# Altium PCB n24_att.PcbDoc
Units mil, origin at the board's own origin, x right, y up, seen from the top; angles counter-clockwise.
Board outline 1125 x 905 mil, 2 copper layers (Top Layer, Bottom Layer); 13 components, 14 nets, 48 pads, 11 vias.
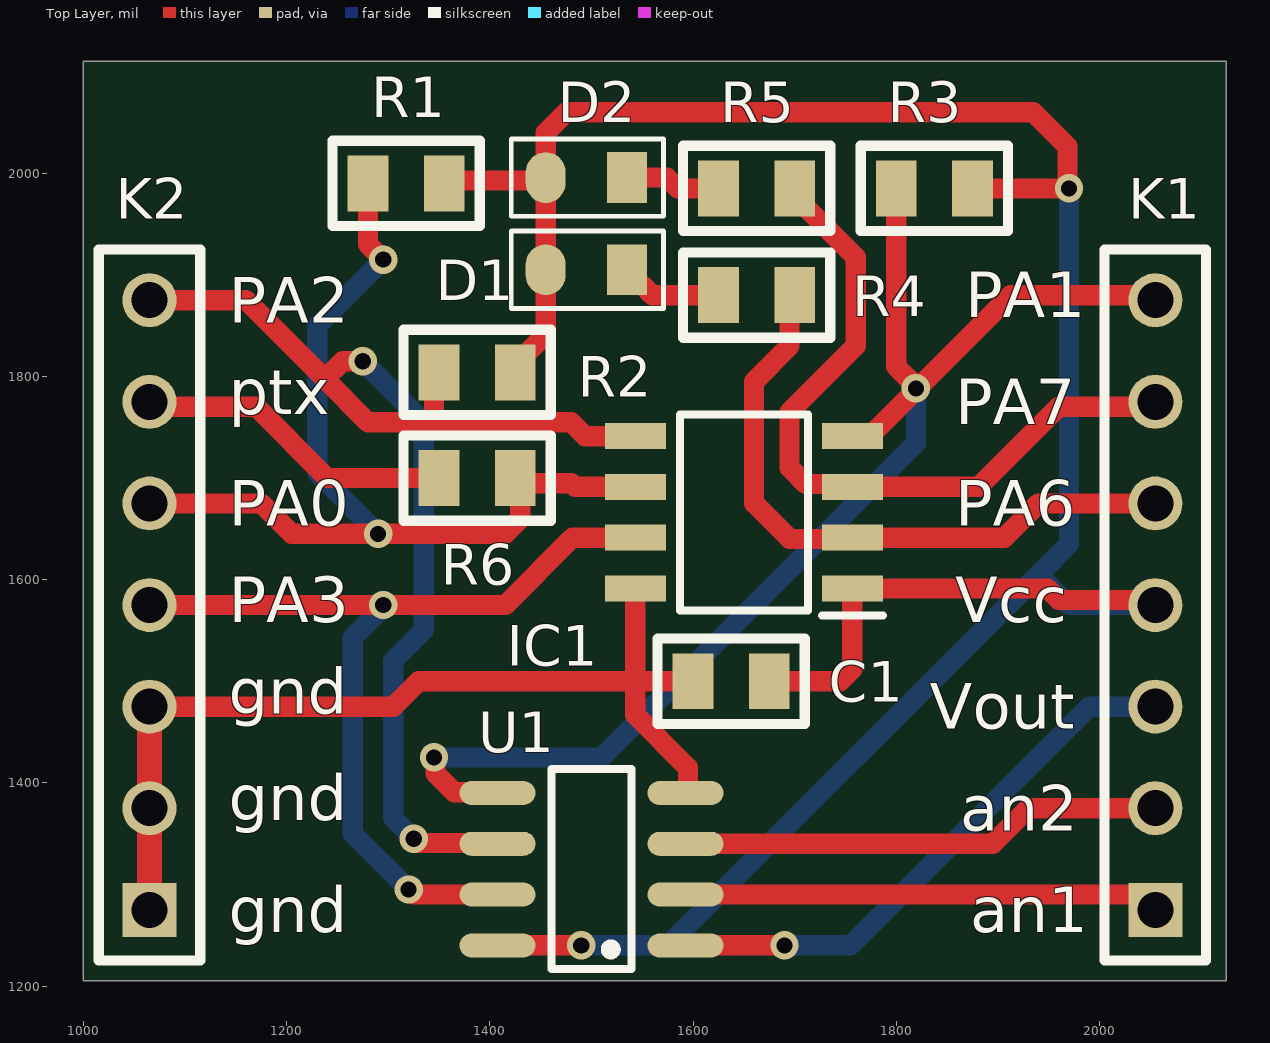
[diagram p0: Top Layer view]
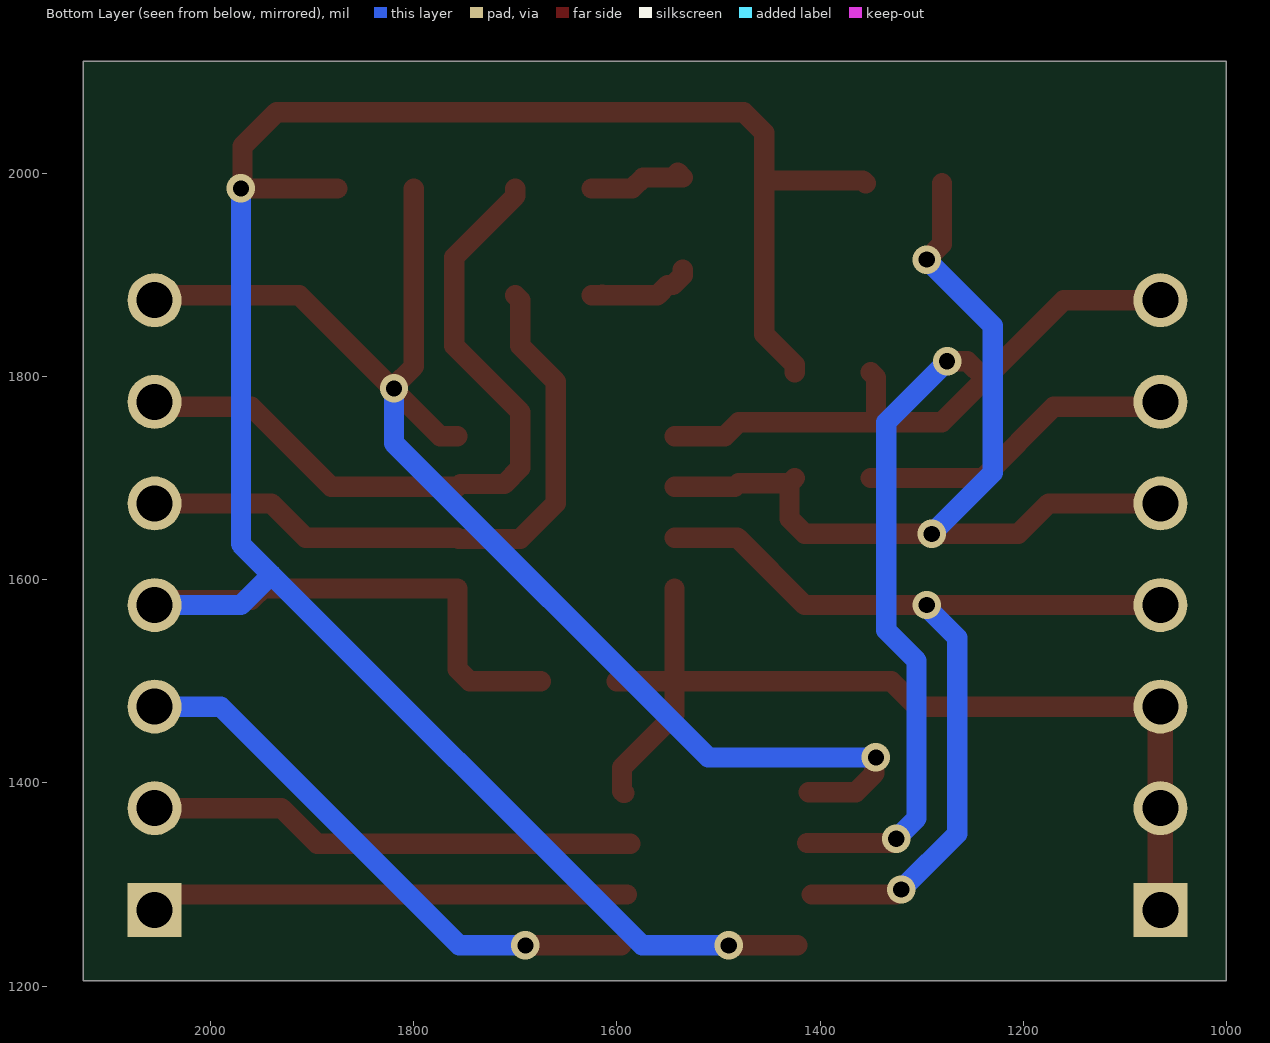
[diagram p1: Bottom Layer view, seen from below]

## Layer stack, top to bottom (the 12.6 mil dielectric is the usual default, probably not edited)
Top Solder: solder mask 0.4, Solder Resist, Dk 3.5
Top Layer: signal copper 1.4
Dielectric 1: dielectric 12.6, FR-4, Dk 4.8
Bottom Layer: signal copper 1.4
Bottom Solder: solder mask 0.4, Solder Resist, Dk 3.5

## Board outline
1000,1205 1000,2110 2125,2110 2125,1925 2125,1575 2125,1205

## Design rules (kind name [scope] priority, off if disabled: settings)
Clearance [All] p1: gap=10 ignorepadtopadclearanceinfootprint=FALSE except(0: Arc-Hole Track-Hole SMDPad-Hole THPad-Hole Via-Hole Fill-Hole Poly-Hole Region-Hole Text-Hole)
HoleSize [All] p1: absolutevalues=TRUE maxlimit=200 minlimit=1 maxpercent=80.000 minpercent=20.000
PolygonConnect [All] p1: connectstyle=Relief reliefconductorwidth=10 reliefentries=4 polygonreliefangle="90 Angle" airgapwidth=10
RoutingVias [All] p1: holewidth=28 width=50 viastyle="Through Hole" minholewidth=16 minwidth=28 maxholewidth=28 maxwidth=50
SilkToSolderMaskClearance [IsPad] p1: minsilkscreentomaskgap=4 clearancetoexposedcopper=TRUE
SolderMaskExpansion [All] p1: expansion=4 istentingtop=FALSE
Width [All] p1: maxlimit=100 minlimit=10 preferedwidth=15
28 further rules are at their usual default settings.

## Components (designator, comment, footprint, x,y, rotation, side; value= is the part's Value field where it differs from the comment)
C1 "cap0805" SM0805 1675,1500 r180 top value=0.1
D1 "LIGHT_SM0805" SM0805_diode 1455,1905 r0 top
D2 "LIGHT_SM0805" SM0805_diode 1455,1995.73 r0 top
IC1 "ATTINY412-SSF" SOIC127P600X175-8N 1650,1666.26 r180 top
K1 "7_PLS_2.54mm" 7_PLS_2.54 2055,1275 r180 top
K2 "7_PLS_2.54mm" 7_PLS_2.54 1065,1275 r180 top
R1 "res0805" SM0805 1355,1990 r180 top value=4K7
R2 "res0805" SM0805 1425,1804.01 r180 top value=4K7
R3 "res0805" SM0805 1875,1985 r180 top value=4K7
R4 "res0805" SM0805 1625,1880 r0 top value=2k
R5 "res0805" SM0805 1625,1985 r0 top value=2k
R6 "res0805" SM0805 1425,1700 r180 top value=1k
U1 "n24rf04" SO8_L 1500,1315 r180 top

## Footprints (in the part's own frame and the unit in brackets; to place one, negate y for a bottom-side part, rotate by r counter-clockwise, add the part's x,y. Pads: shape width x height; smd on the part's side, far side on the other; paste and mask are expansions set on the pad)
7_PLS_2.54 [mm] "PLS row"
  rect 1.35x1.35 hole 0.9: 1(0,0)
  round 1.35 hole 0.9: 2(0,-2.54) 3(0,-5.08) 4(0,-7.62) 5(0,-10.16) 6(0,-12.7) 7(0,-15.24)
  silkscreen extent -1.27,-16.51 1.27,1.27
SM0805 [mil]
  rect 40x55 smd: 1(0,0) 2(75,0)
  silkscreen extent -35,-42 110,42
SM0805_diode [mm]
  oval 1x1.27 smd: 1(0,0)
  rect 1x1.27 smd: 2(2.032,0)
  silkscreen extent -0.86,-0.97 2.95,0.97
SO8_L [mm] "SOIC, 8-Leads, Body 4.9x3.9mm, Pitch 1.27mm, IPC High Density"
  oval 1.9x0.6 smd: 1(-2.35,1.905) 2(-2.35,0.635) 3(-2.35,-0.635) 4(-2.35,-1.905) 5(2.35,-1.905) 6(2.35,-0.635) 7(2.35,0.635) 8(2.35,1.905)
  silkscreen extent -1,-2.5 1,2.5, body extent -2,-2.5 2,2.5, height 1.75
SOIC127P600X175-8N [mm]
  rect 1.525x0.65 smd: 1(-2.712,1.905) 2(-2.712,0.635) 3(-2.712,-0.635) 4(-2.712,-1.905) 5(2.712,-1.905) 6(2.712,-0.635) 7(2.712,0.635) 8(2.712,1.905)
  silkscreen extent -3.47,-2.45 1.6,2.58, body extent -3,-2.45 3,2.45, height 1.75

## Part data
C1: "Capacitor"
IC1: "Integrated Circuit", Manufacturer_Name=Microchip, Mouser Part Number=579-ATTINY412-SSF
K1 K2: "7 pin vertical 2.54mm"
R1 R2 R3 R4 R5 R6: "Resistor"
U1: "eeprom & nfc tag"

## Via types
v1: diameter 28, hole 16, Top Layer to Bottom Layer, 11 vias

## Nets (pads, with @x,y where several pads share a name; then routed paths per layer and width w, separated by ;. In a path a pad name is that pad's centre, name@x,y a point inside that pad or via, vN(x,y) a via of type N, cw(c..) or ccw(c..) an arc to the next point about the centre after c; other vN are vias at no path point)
an1: K1.1 U1.2 | length 471.1
  Top Layer w20: U1.2@1590.1,1290 2040,1290 K1.1
an2: K1.2 U1.3 | length 482.8
  Top Layer w20: U1.3@1586.74,1340 1895,1340 1930,1375 K1.2
GND: C1.2 IC1.8 K2.1 K2.2 K2.3 U1.4 | length 969.6
  Top Layer w20: K2.3 1305,1475 1330,1500 1543.23,1500 ; IC1.8 1543.23,1500 ; U1.4 1593.33,1390 1595,1391.67 1595,1415 1543.23,1466.77 1543.23,1500 ; C1.2 1543.23,1500
  Top Layer w25: K2.1 K2.2 K2.3
NetD1_2: D1.2 R4.1 | length 104.2
  Top Layer w20: D1.2 1535,1899.69 1544.69,1890 1550,1890 1560,1880 R4.1@1615,1880 ; R4.1@1614.51,1880.49 R4.1@1615,1880 ; R4.1 R4.1@1615,1880
NetD2_2: D2.2 R5.1 | length 101.5
  Top Layer w20: D2.2@1540,2000.73 D2.2 1574.27,1995.73 1585,1985 R5.1
NetK2_6: K2.6 R6.2 | length 316.1
  Top Layer w20: K2.6 1070,1770 1170,1770 1240,1700 R6.2
rx: IC1.3 K1.6 R5.2 | length 729.2
  Top Layer w20: R5.2 1700,1977.5 1760,1917.5 1760,1830 1695,1765 1695,1710 1710.94,1694.06 1753.98,1694.06 IC1.3 1881.26,1691.26 1960,1770 2050,1770 K1.6
scl: IC1.5 K2.7 R2.2 U1.6 | length 1234.7
  Top Layer w20: K2.7 1160,1875 1237.5,1797.5 ; v1(1275,1815) 1255,1815 1237.5,1797.5 ; v1(1325,1345) 1329.31,1340.69 U1.6@1412.85,1340.69 ; R2.2 1345,1799.01 1345,1755 ; IC1.5 1493.74,1741.26 1480,1755 1345,1755 ; 1237.5,1797.5 1280,1755 1345,1755
  Bottom Layer w20: v1(1275,1815) 1335,1755 1335,1550 1305,1520 1305,1365 v1(1325,1345)
sda: IC1.4 K1.7 R3.2 U1.5 | length 1309
  Top Layer w20: v1(1345,1425) 1346.53,1423.47 1346.53,1409.13 1364.96,1390.69 U1.5@1411.28,1390.69 ; IC1.4 1774,1741.26 v1@1820.16,1787.42 ; R3.2 1800,1809.75 1820.16,1789.59 v1@1820.16,1787.42 ; K1.7 2050,1880 1912.73,1880 v1@1820.16,1787.42
  Bottom Layer w20: v1(1345,1425) 1510,1425 1819.35,1734.35 v1(1819.35,1788.23)
tx: IC1.2 K1.5 R4.2 | length 645.6
  Top Layer w20: R4.2 1695,1875 1695,1830 1660,1795 1660,1675 1695,1640 1755.51,1640 IC1.2 1906.26,1641.26 1940,1675 K1.5
updi: IC1.6 K2.5 R1.2 R6.1 | length 943.5
  Top Layer w20: K2.5 1175,1675 1205,1645 v1(1290,1645) 1415,1645 1430,1660 R6.1@1430,1695 ; R1.2 1280,1930 v1(1295,1915) ; R6.1 R6.1@1430,1695 ; IC1.6 1483.74,1691.26 1480,1695 R6.1@1430,1695
  Bottom Layer w20: v1(1290,1645) 1230,1705 1230,1850 v1(1295,1915)
VCC: C1.1 D1.1 D2.1 IC1.1 K1.4 R1.1 R2.1 R3.1 U1.8 | length 2683.2
  Top Layer w20: R1.1 1357.87,1992.87 1452.13,1992.87 D2.1 ; U1.8@1422.48,1240 v1(1490,1240) ; R2.1 1425,1811.51 1455,1841.51 D1.1 D2.1 ; C1.1 1745,1500 1756.77,1511.77 IC1.1 1948.74,1591.26 1960,1580 2050,1580 K1.4 ; R3.1 v1(1970,1985) 1968.47,1986.53 1968.47,2026.53 1935,2060 1475,2060 1455,2040 D2.1
  Bottom Layer w20: v1(1490,1240) 1575,1240 1940,1605 ; v1(1970,1985) 1970,1635 1940,1605 ; K1.4 1970,1575 1940,1605
vout: K1.3 U1.1 | length 556.8
  Top Layer w20: U1.1@1595.49,1240 v1(1690,1240)
  Bottom Layer w20: v1(1690,1240) 1755,1240 1990,1475 K1.3
wp: IC1.7 K2.4 U1.7 | length 911.1
  Top Layer w20: K2.4 v1(1295,1575) 1415,1575 1481.26,1641.26 IC1.7 ; v1(1320,1295) 1325,1290 U1.7@1408.14,1290
  Bottom Layer w20: v1(1295,1575) 1295,1572.84 1265,1542.84 1265,1350 v1(1320,1295)

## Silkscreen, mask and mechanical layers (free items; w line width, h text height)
Top Overlay:
  text "PA1" at 1868,1858 h45
  text "PA2" at 1143,1853 h45
  text "ptx" at 1143,1763 h45
  text "PA7" at 1858,1753 h45
  text "PA0" at 1143,1653 h45
  text "PA6" at 1858,1653 h45
  text "PA3" at 1143,1558 h45
  text "Vcc" at 1858,1558 h45
  text "gnd" at 1143,1468 h45
  text "Vout" at 1833,1453 h45
  text "gnd" at 1143,1363 h45
  text "an2" at 1863,1353 h45
  text "gnd" at 1143,1253 h45
  text "an1" at 1873,1253 h45
Mechanical 1:
  lines w10: 1000,1205 2125,1205 2125,2110 1000,2110 1000,1205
